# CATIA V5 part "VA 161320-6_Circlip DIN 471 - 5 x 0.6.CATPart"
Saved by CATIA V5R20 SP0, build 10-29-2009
Part number: VA 161320-6_Circlip DIN 471 - 5 x 0.6
Revision: ANY
Definition: UNKNOWN
Nomenclature: VA 161320-6_Circlip DIN 471 - 5 x 0.6
Source: Unknown
Bounding box of the stored display mesh (mm): x -3.167 to 3.167, y -4.898 to 3.345, z -0.6 to 0
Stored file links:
  C:\Users\Utente\Desktop\IO LAVORO\3D X SITO CF\CUMSA\3D files VA\VA 161320\VA 161320-6_Circlip DIN 471 - 5 x 0.6.CATPart
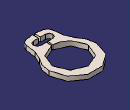
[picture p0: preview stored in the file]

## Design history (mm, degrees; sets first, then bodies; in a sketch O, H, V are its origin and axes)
Body1 "Notch" (main body)
  Solid1: solid without history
